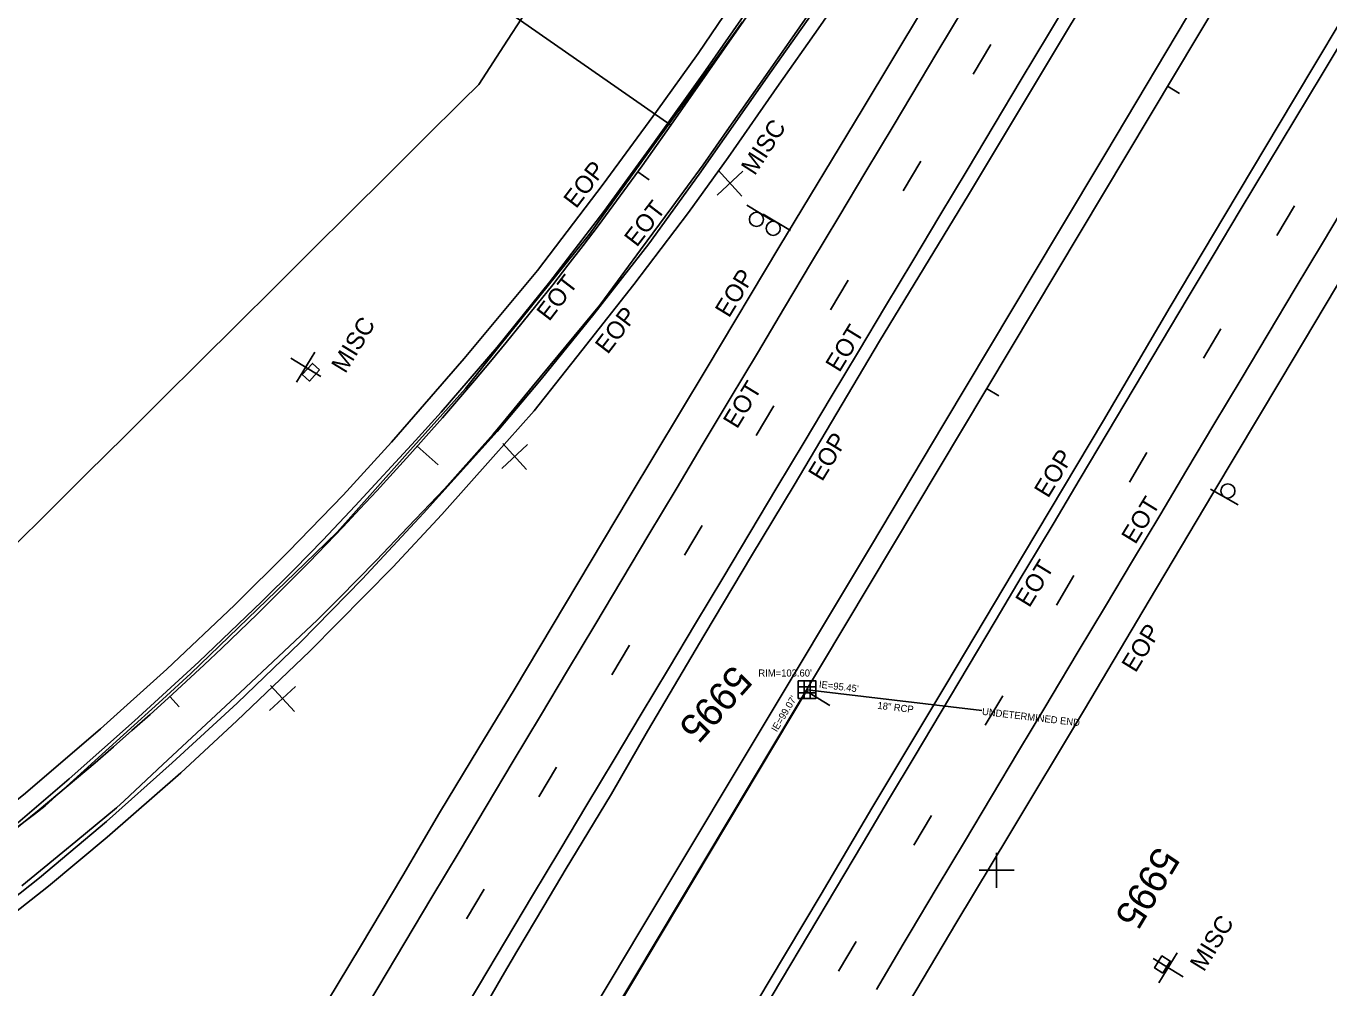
# Model space of a CAD drawing. Extents: x 2132221 to 2141942, y 535736 to 547298.
# Drawn here: x 2138558.7 to 2138928.5, y 541740.8 to 542013.9 of the extents above; entities that cross this region are included whole.
import ezdxf

# ---------------------------------------------------------------- set-up
doc = ezdxf.new("R2010")
doc.units = 0
for name, color, linetype in [('RD_EX_BldgApp', 7, 'Continuous'), ('RD_EX_Conc', 7, 'Continuous'), ('RD_EX_DR_Inlet', 7, 'Continuous'), ('RD_EX_DR_Inlet_txCode', 7, 'Continuous'), ('RD_EX_DR_Pipe', 7, 'Continuous'), ('RD_EX_DR_Pipe_txCode', 7, 'Continuous'), ('RD_EX_GuardRail', 7, 'Continuous'), ('RD_EX_Misc', 7, 'Continuous'), ('RD_EX_Misc_txCode', 7, 'Continuous'), ('RD_EX_Road', 7, 'Continuous'), ('RD_EX_Road_txCode', 7, 'Continuous'), ('RD_EX_VEG', 7, 'Continuous'), ('RD_HC_Cl', 7, 'Continuous'), ('RD_HC_Data', 7, 'Continuous'), ('RD_HC_Data_Tic', 7, 'Continuous'), ('RD_HC_TX_Sta50', 7, 'Continuous')]:
    doc.layers.add(name, color=color, linetype=linetype)

msp = doc.modelspace()

# ---------------------------------------------------------------- linework, layer by layer
at = {"layer": 'RD_EX_BldgApp'}
for p, q in [((2138770.96, 541958.35), (2138763.28, 541963.04)), ((2138775.71, 541955.84), (2138767.99, 541960.47)), ((2138894.93, 541882.35), (2138902.75, 541877.89))]:
    msp.add_line(p, q, dxfattribs=at)
for centre in [(2138766.05, 541958.98), (2138770.8, 541956.43), (2138899.86, 541881.87)]:
    msp.add_circle(centre, 2, dxfattribs=at)
at = {"layer": 'RD_EX_Conc'}
for points in [[(2138751.62, 542001.29), (2138764.44, 542019.67), (2138780.01, 542042.02), (2138794.03, 542062.18)], [(2138770.39, 542001.23), (2138792.82, 542033.08), (2138807.11, 542053.36)], [(2138634.91, 541859.67), (2138642.95, 541867.95), (2138652.19, 541877.69), (2138669.29, 541896.24), (2138676.52, 541904.28), (2138692.44, 541922.65), (2138707.43, 541941.27), (2138722.72, 541961.21), (2138737.1, 541980.95), (2138751.62, 542001.29)], [(2138654.13, 541856.83), (2138671.59, 541875.54), (2138692.43, 541898.77), (2138704.99, 541913.6), (2138719.94, 541932.04), (2138735.47, 541952), (2138749.77, 541971.84), (2138770.39, 542001.23)], [(2138320.66, 541646.24), (2138343.12, 541656.01), (2138365.46, 541666.32), (2138387.76, 541677.52), (2138409.22, 541688.97), (2138430.74, 541701.11), (2138451.71, 541713.76), (2138472.54, 541726.85), (2138492.99, 541740.37), (2138513.17, 541754.66), (2138532.93, 541769.02), (2138552.43, 541784.26), (2138571.02, 541800.11), (2138589.56, 541816.64), (2138607.73, 541833.33), (2138625.65, 541850.53), (2138634.91, 541859.67)], [(2138326.85, 541631.63), (2138349.75, 541641.63), (2138372.34, 541652.17), (2138394.8, 541663.21), (2138416.86, 541675.11), (2138438.6, 541687.28), (2138460.13, 541700.22), (2138481.26, 541713.49), (2138501.99, 541727.45), (2138522.49, 541741.75), (2138542.74, 541756.38), (2138562.52, 541772.02), (2138581.55, 541788.07), (2138600.17, 541804.67), (2138618.62, 541821.66), (2138636.61, 541838.98), (2138654.13, 541856.83)]]:
    msp.add_lwpolyline(points, dxfattribs=at)
at = {"layer": 'RD_EX_DR_Inlet'}
for p, q in [((2138779.62, 541827.96), (2138779.62, 541822.96)), ((2138781.32, 541827.96), (2138781.32, 541822.96)), ((2138777.92, 541826.26), (2138782.92, 541826.26)), ((2138777.92, 541824.56), (2138782.92, 541824.56))]:
    msp.add_line(p, q, dxfattribs=at)
msp.add_lwpolyline([(2138777.92, 541822.96), (2138777.92, 541827.96), (2138782.92, 541827.96), (2138782.92, 541822.96)], close=True, dxfattribs=at)
at = {"layer": 'RD_EX_DR_Pipe'}
msp.add_lwpolyline([(2138470.52, 541306.69), (2138780.46, 541825.4), (2138829.99, 541819.57)], dxfattribs=at)
at = {"layer": 'RD_EX_GuardRail'}
for points in [[(2138851.75, 541955.34), (2138865.25, 541977.82), (2138891.04, 542021.08), (2138921.51, 542071.79), (2138957.23, 542131.41), (2138984.41, 542176.81), (2139016.58, 542230.45), (2139056.94, 542297.59), (2139088.78, 542351.41), (2139113.89, 542392.68), (2139145.32, 542445.41), (2139147.37, 542448.82)], [(2138741.42, 541771.02), (2138765.68, 541811.44), (2138798.43, 541865.99), (2138819.28, 541900.91), (2138851.75, 541955.34)], [(2138741.42, 541771.02), (2138732.99, 541756.82), (2138725.11, 541743.68), (2138717.15, 541730.38), (2138709.08, 541716.89), (2138701.01, 541703.4), (2138694.44, 541692.3), (2138683.85, 541674.67), (2138669.13, 541649.92), (2138652.79, 541622.56), (2138636.97, 541596.05), (2138620.77, 541569.14)]]:
    msp.add_lwpolyline(points, dxfattribs=at)
at = {"layer": 'RD_EX_Misc'}
for p, q in [((2138827.58, 542000.24), (2138832.58, 542008.63)), ((2138754.86, 541965.86), (2138762.21, 541972.65)), ((2138755.14, 541972.93), (2138761.93, 541965.58)), ((2138807.72, 541967.11), (2138812.71, 541975.5)), ((2138913.79, 541954.39), (2138918.79, 541962.78)), ((2138787.09, 541933.34), (2138792.09, 541941.73)), ((2138892.9, 541919.53), (2138897.9, 541927.92)), ((2138635.5, 541912.73), (2138640.72, 541921.26)), ((2138642.38, 541914.39), (2138633.85, 541919.61)), ((2138765.99, 541897.63), (2138770.98, 541906.02)), ((2138693.75, 541888.24), (2138701.1, 541895.03)), ((2138694.04, 541895.31), (2138700.82, 541887.96)), ((2138871.89, 541884.37), (2138876.88, 541892.76)), ((2138745.63, 541863.69), (2138750.63, 541872.08)), ((2138851.19, 541849.47), (2138856.18, 541857.85)), ((2138725.04, 541829.71), (2138730.03, 541838.1)), ((2138627.87, 541819.55), (2138635.22, 541826.33)), ((2138628.16, 541826.61), (2138634.94, 541819.26)), ((2138830.96, 541815.35), (2138835.96, 541823.73)), ((2138704.31, 541795.05), (2138709.3, 541803.43)), ((2138810.75, 541781.3), (2138815.74, 541789.69)), ((2138834.23, 541769.17), (2138834.23, 541779.17)), ((2138829.23, 541774.17), (2138839.23, 541774.17)), ((2138683.77, 541760.42), (2138688.77, 541768.81)), ((2138789.33, 541745.57), (2138794.33, 541753.95)), ((2138880.29, 541742.25), (2138885.51, 541750.78)), ((2138887.17, 541743.9), (2138878.64, 541749.12))]:
    msp.add_line(p, q, dxfattribs=at)
for points in [[(2138679.41, 541728.41), (2138687.11, 541741.28), (2138694.82, 541754.15), (2138702.53, 541767.02), (2138710.23, 541779.89), (2138717.94, 541792.76), (2138725.64, 541805.63), (2138733.35, 541818.49), (2138741.06, 541831.36), (2138748.76, 541844.23), (2138756.47, 541857.1), (2138764.17, 541869.97), (2138771.88, 541882.84), (2138779.59, 541895.71), (2138787.29, 541908.58), (2138795, 541921.45), (2138802.7, 541934.32), (2138810.41, 541947.19), (2138818.12, 541960.06), (2138825.82, 541972.93), (2138833.53, 541985.79), (2138841.23, 541998.66), (2138848.94, 542011.53), (2138856.65, 542024.4)], [(2138784.08, 542021.9), (2138775.49, 542009.61), (2138766.9, 541997.31), (2138758.31, 541985.02), (2138750.93, 541974.45), (2138742.03, 541962.38), (2138733.12, 541950.31), (2138724.22, 541938.23), (2138721.57, 541934.63), (2138712.02, 541923.07), (2138702.47, 541911.5), (2138692.92, 541899.93), (2138691.29, 541897.95), (2138681.31, 541886.75), (2138677.53, 541882.52), (2138667.2, 541871.65), (2138658.14, 541862.13), (2138647.6, 541851.46), (2138641.38, 541845.16), (2138630.42, 541834.91), (2138619.47, 541824.67), (2138608.51, 541814.42), (2138597.55, 541804.18), (2138586.6, 541793.93), (2138584.4, 541791.87), (2138572.82, 541782.34), (2138569.14, 541779.31), (2138557.56, 541769.78)], [(2138650.85, 541727.93), (2138658.55, 541740.81), (2138666.25, 541753.68), (2138673.95, 541766.56), (2138681.65, 541779.43), (2138689.34, 541792.3), (2138697.04, 541805.18), (2138704.74, 541818.05), (2138712.44, 541830.93), (2138720.14, 541843.8), (2138727.84, 541856.67), (2138735.53, 541869.55), (2138743.23, 541882.42), (2138750.93, 541895.3), (2138758.63, 541908.17), (2138766.33, 541921.04), (2138774.02, 541933.92), (2138781.72, 541946.79), (2138789.42, 541959.66), (2138797.12, 541972.54), (2138804.82, 541985.41), (2138812.52, 541998.29), (2138817.29, 542006.26), (2138824.98, 542019.14)], [(2138549.13, 541781.09), (2138561.09, 541790.15), (2138564.15, 541792.46), (2138575.25, 541802.54), (2138586.36, 541812.63), (2138597.47, 541822.71), (2138605.52, 541830.02), (2138616.29, 541840.45), (2138627.07, 541850.88), (2138637.85, 541861.32), (2138647.05, 541870.22), (2138657.04, 541881.41), (2138667.03, 541892.61), (2138677.02, 541903.8), (2138683.42, 541910.97), (2138692.82, 541922.66), (2138702.22, 541934.35), (2138711.62, 541946.04), (2138718.63, 541954.76), (2138727.41, 541966.92), (2138736.19, 541979.08), (2138744.97, 541991.24), (2138753.75, 542003.41), (2138762.13, 542015.02)], [(2138765.45, 541730.17), (2138773.13, 541743.06), (2138780.81, 541755.95), (2138788.48, 541768.83), (2138796.16, 541781.72), (2138803.84, 541794.61), (2138810.8, 541806.29), (2138818.48, 541819.18), (2138826.15, 541832.06), (2138833.83, 541844.95), (2138841.51, 541857.84), (2138842.55, 541859.59), (2138850.23, 541872.48), (2138857.91, 541885.37), (2138865.58, 541898.25), (2138873.26, 541911.14), (2138880.94, 541924.03), (2138888.62, 541936.91), (2138895.66, 541948.74), (2138903.39, 541961.59), (2138911.12, 541974.45), (2138918.85, 541987.3), (2138926.58, 542000.16), (2138934.32, 542013.01)], [(2138934.38, 541965.07), (2138926.68, 541952.2), (2138918.99, 541939.33), (2138911.29, 541926.45), (2138903.59, 541913.58), (2138895.89, 541900.7), (2138888.2, 541887.83), (2138880.5, 541874.95), (2138872.8, 541862.08), (2138865.11, 541849.2), (2138857.41, 541836.33), (2138849.71, 541823.46), (2138848.17, 541820.88), (2138840.47, 541808.01), (2138832.78, 541795.13), (2138825.08, 541782.26), (2138817.38, 541769.38), (2138809.69, 541756.51), (2138807.74, 541753.25), (2138800.11, 541740.33)]]:
    msp.add_lwpolyline(points, dxfattribs=at)
for points in [[(2138642.04, 541916.28), (2138639.16, 541913.08), (2138637.13, 541914.9), (2138640.01, 541918.1)], [(2138881.43, 541745.01), (2138879.07, 541746.46), (2138881.16, 541749.87), (2138883.52, 541748.42)]]:
    msp.add_lwpolyline(points, close=True, dxfattribs=at)
at = {"layer": 'RD_EX_Road'}
for points in [[(2138749.53, 542006.05), (2138760.48, 542022.31), (2138777.23, 542046.64), (2138789.63, 542064.95), (2138809.23, 542093.07), (2138821.18, 542111.68), (2138833.17, 542129.28), (2138849.99, 542152.07), (2138862.29, 542170.4), (2138870.68, 542182.24), (2138882.29, 542199.27), (2138900.35, 542225.88), (2138912.33, 542242.73), (2138926.34, 542262.07), (2138943.42, 542286.29), (2138961.21, 542311.72), (2138978.94, 542337.3), (2138996.16, 542362.03), (2139011.52, 542383.62), (2139030.71, 542411.27), (2139049.59, 542437.98), (2139062.48, 542457.08), (2139081.59, 542484.58), (2139095.42, 542504.19)], [(2139134.59, 542480.14), (2139117.82, 542452.18), (2139094.47, 542413.68), (2139071.14, 542374.55), (2139048.53, 542337.23), (2139029.44, 542304.84), (2139009.21, 542271.38), (2138989.73, 542238.46), (2138969.33, 542204.58), (2138948.78, 542169.73), (2138929.06, 542136.92), (2138909.7, 542105.48), (2138889.47, 542071.54), (2138872.98, 542043.32), (2138855.21, 542014.19), (2138826.2, 541965.96)], [(2138883.52, 541934.18), (2138898.95, 541960.2), (2138918.44, 541992.8), (2138938.06, 542025.7), (2138960.66, 542063.6), (2138982.75, 542100.59), (2138999.53, 542128.76), (2139020.67, 542163.95), (2139041.4, 542198.65), (2139058.21, 542226.76), (2139075.66, 542256.28), (2139095.39, 542289.29), (2139116.91, 542325.43), (2139138.66, 542361.84), (2139149.55, 542379.94), (2139189.43, 542446.45)], [(2138796.06, 541990.06), (2138813.42, 542019.03), (2138832.35, 542050.36), (2138853.78, 542086.77), (2138874.23, 542120.12), (2138891.32, 542149.29), (2138899.1, 542162.43), (2138911.88, 542186.83), (2138920.74, 542202.56), (2138918.06, 542205.35), (2138898.73, 542178.21), (2138876.89, 542147.26), (2138855.85, 542117.18), (2138834.91, 542086.92), (2138816.65, 542060.59), (2138800.03, 542036.82), (2138783.58, 542013.05), (2138772.54, 541997.33)], [(2138648.79, 541880.72), (2138662.43, 541895.71), (2138683.07, 541919.45), (2138703.92, 541944.51), (2138722.52, 541968.93), (2138737.72, 541989.56), (2138749.53, 542006.05)], [(2138662.83, 541860.24), (2138676.79, 541875.17), (2138691.35, 541891.54), (2138702.98, 541904.66), (2138716.5, 541921.74), (2138731.27, 541940.45), (2138746.81, 541960.89), (2138757.98, 541976.53), (2138772.54, 541997.33)], [(2138796.06, 541990.06), (2138772.71, 541951.5), (2138751.74, 541916.46), (2138729.95, 541880.13), (2138697.28, 541825.4)], [(2138826.2, 541965.96), (2138800.94, 541924.36), (2138776.77, 541883.49), (2138764.62, 541863.45), (2138751.43, 541841.18), (2138735.12, 541813.67), (2138724.94, 541795.88)], [(2138933.88, 541945.35), (2138914.89, 541913.44)], [(2138883.52, 541934.18), (2138864.6, 541901.84), (2138841.86, 541863.84), (2138819.81, 541826.83), (2138798.8, 541791.8), (2138784.41, 541767.43), (2138769.69, 541742.7)], [(2138914.89, 541913.44), (2138895.6, 541881.14), (2138877.5, 541850.73), (2138859.13, 541819.86), (2138837.67, 541784.01), (2138822.96, 541759.59), (2138811.33, 541740), (2138799.45, 541720.23)], [(2138319.72, 541650.84), (2138341.99, 541661.22), (2138365.85, 541672.43), (2138386.58, 541682.71), (2138407.18, 541693.44), (2138431.12, 541707.27), (2138454.48, 541721.2), (2138472.09, 541732.56), (2138494.83, 541747.89), (2138516.25, 541763.27), (2138534.97, 541777.14), (2138558.6, 541796.04), (2138579.91, 541814.38), (2138598.67, 541831.29), (2138617.88, 541849.47), (2138633.25, 541864.69), (2138648.79, 541880.72)], [(2138317.42, 541624.05), (2138338.77, 541633.03), (2138357.11, 541641.14), (2138373.84, 541648.73), (2138396.68, 541660.2), (2138418.52, 541671.85), (2138440.73, 541684.35), (2138462.3, 541697.15), (2138483.42, 541710.68), (2138504.29, 541724.54), (2138524.92, 541739.2), (2138544.46, 541753.5), (2138565.11, 541769.66), (2138581.74, 541783.59), (2138602.69, 541801.88), (2138618.54, 541816.61), (2138639.24, 541836.38), (2138662.83, 541860.24)], [(2138548.1, 541576.55), (2138563.93, 541602.75), (2138573.59, 541618.82), (2138583.77, 541636.3), (2138596.7, 541657.83), (2138601.61, 541666.1), (2138613.51, 541685.67), (2138628.6, 541710.63), (2138640.94, 541731.58), (2138653.63, 541752.56), (2138665.67, 541772.73), (2138676.11, 541790.53), (2138687.24, 541808.93), (2138697.28, 541825.4)], [(2138596.66, 541581.78), (2138604.32, 541594.67), (2138608.22, 541601.23), (2138615.95, 541614.08), (2138618.27, 541617.93), (2138626, 541630.78), (2138632.04, 541640.8), (2138639.75, 541653.67), (2138646.02, 541664.14), (2138653.77, 541676.98), (2138660.54, 541688.2), (2138668.19, 541701.1), (2138671.3, 541706.35), (2138679.12, 541719.15), (2138686.38, 541731.02), (2138693.9, 541743.99), (2138698.01, 541751.08), (2138705.67, 541763.98), (2138712, 541774.66), (2138719.81, 541787.47), (2138724.94, 541795.88)], [(2138468.55, 541237.79), (2138481.36, 541259.3), (2138492.75, 541278.31), (2138508.8, 541304.94), (2138524.75, 541331.76), (2138540.54, 541357.96), (2138552.03, 541377.33), (2138569.58, 541406.74), (2138581.68, 541427.05), (2138605.55, 541467.18), (2138621.85, 541494.63), (2138643.05, 541530.22), (2138654.92, 541550.18), (2138673.72, 541581.7), (2138687.48, 541604.69), (2138699.32, 541624.63), (2138717.19, 541654.69), (2138728.43, 541673.42), (2138742.06, 541696.3), (2138756.14, 541719.99), (2138769.69, 541742.7)]]:
    msp.add_lwpolyline(points, dxfattribs=at)
at = {"layer": 'RD_EX_VEG'}
msp.add_lwpolyline([(2138554.82, 541865.74), (2138565.46, 541876.31), (2138576.1, 541886.88), (2138586.74, 541897.46), (2138597.38, 541908.03), (2138608.02, 541918.6), (2138618.66, 541929.17), (2138629.31, 541939.74), (2138639.95, 541950.32), (2138650.59, 541960.89), (2138661.23, 541971.46), (2138671.87, 541982.03), (2138682.51, 541992.6), (2138687.22, 541997.29), (2138695.39, 542009.87), (2138703.56, 542022.45)], dxfattribs=at)
at = {"layer": 'RD_HC_Cl'}
for p, q in [((2139719.79, 543396.28), (2136851.48, 538600.7)), ((2139204.23, 542649.25), (2138741.77, 541985.73))]:
    msp.add_line(p, q, dxfattribs=at)
msp.add_arc((2137944.04, 542541.74), 972.38, 220.32405, 325.12405, dxfattribs=at)
at = {"layer": 'RD_HC_Data'}
msp.add_line((2138741.77, 541985.73), (2138634.3, 542060.64), dxfattribs=at)
at = {"layer": 'RD_HC_Data_Tic'}
for p, q in [((2138882.72, 541996.76), (2138886.15, 541994.71)), ((2138732.38, 541972.5), (2138735.63, 541970.16)), ((2138831.39, 541910.94), (2138834.82, 541908.89)), ((2138669.78, 541894.58), (2138675.75, 541889.25)), ((2138780.06, 541825.12), (2138786.92, 541821.01)), ((2138599.51, 541823.49), (2138602.21, 541820.54))]:
    msp.add_line(p, q, dxfattribs=at)

# ---------------------------------------------------------------- texts
at = {"layer": 'RD_EX_DR_Inlet_txCode'}
msp.add_text("RIM=103.60'", height=2, dxfattribs=at).set_placement((2138766.6, 541829.19))
for s, rotation, p in [("IE=95.45'", 353.2835, (2138783.7, 541826.03)), ("IE=99.07'", 59.1157, (2138771.82, 541813.29)), ('UNDETERMINED END', 353.2835, (2138829.99, 541818.33))]:
    msp.add_text(s, height=2, rotation=rotation, dxfattribs=at).set_placement(p)
at = {"layer": 'RD_EX_DR_Pipe_txCode'}
msp.add_text('18" RCP', height=2, rotation=353.2835, dxfattribs=at).set_placement((2138800.3, 541820.04))
at = {"layer": 'RD_EX_Misc_txCode'}
for s, rotation, p in [(' MISC', 57.0946, (2138764.55, 541969.64)), ('EOT', 52.4153, (2138732.09, 541950.89)), ('EOT', 52.4153, (2138707.21, 541929.81)), ('MISC', 58.5343, (2138649.34, 541915)), ('EOT', 58.5343, (2138789.6, 541915.3)), ('EOT', 58.5343, (2138760.54, 541899.28)), ('EOT', 58.5343, (2138873.59, 541866.48)), ('EOT', 58.5343, (2138843.5, 541848.51)), ('MISC', 58.5343, (2138893.04, 541745.14))]:
    msp.add_text(s, height=5, rotation=rotation, dxfattribs=at).set_placement(p)
at = {"layer": 'RD_EX_Road_txCode'}
for rotation, p in [(52.5664, (2138714.87, 541961.82)), (58.5343, (2138758.25, 541930.79)), (52.5664, (2138723.82, 541920.46)), (58.5343, (2138784.69, 541884.34)), (58.5343, (2138848.83, 541879.61)), (58.5343, (2138873.65, 541830.05))]:
    msp.add_text('EOP', height=5, rotation=rotation, dxfattribs=at).set_placement(p)
at = {"layer": 'RD_HC_TX_Sta50'}
for rotation, p in [(228.2758, (2138759.45, 541832.86)), (239.1157, (2138879.73, 541781.37))]:
    msp.add_text('5995', height=8, rotation=rotation, dxfattribs=at).set_placement(p)

doc.saveas('drawing.dxf')
